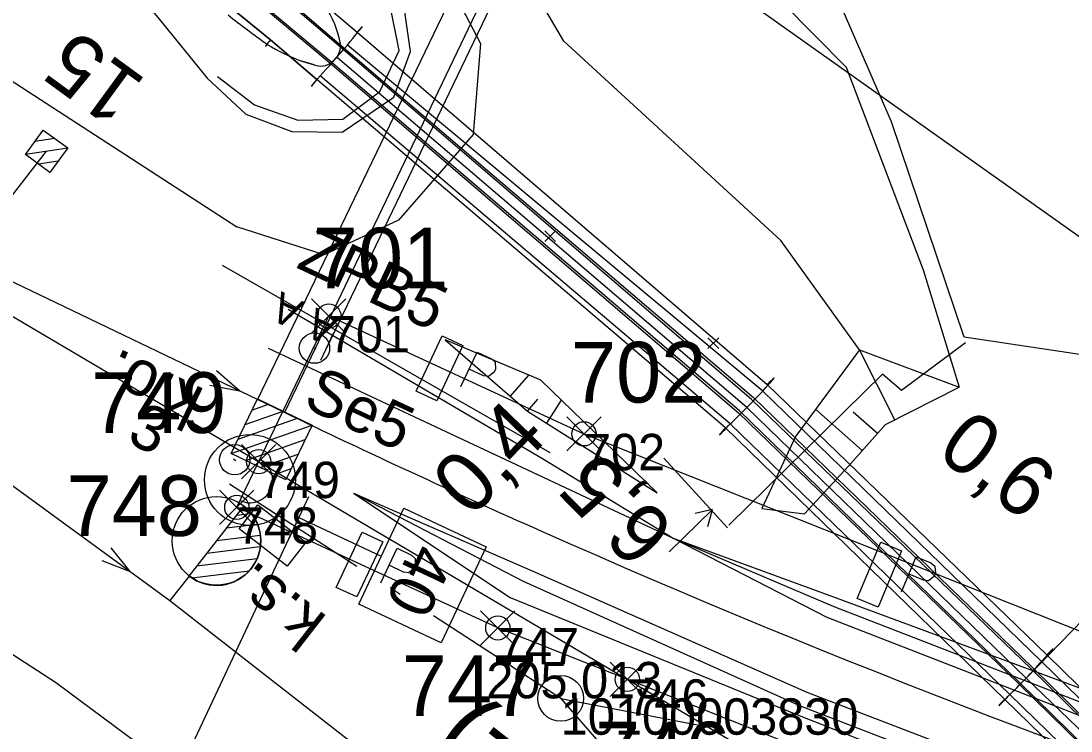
# Model space of a CAD drawing. Extents: x -800194 to -799078, y -1007177 to -1006597.
# Drawn here: x -799787.82 to -799753.2, y -1006976.93 to -1006953.52 of the extents above; entities that cross this region are included whole.
import ezdxf

# ---------------------------------------------------------------- set-up
doc = ezdxf.new("R2010")
doc.units = 0
for name, color, linetype in [('02_Osa_koleje', 7, 'Continuous'), ('_návrh', 7, 'Continuous'), ('_popvyt', 7, 'Continuous'), ('Obvod stavby', 7, 'Continuous'), ('Vrstva 11', 7, 'Continuous'), ('Vrstva 13', 7, 'Continuous'), ('Vrstva 16', 7, 'Continuous'), ('Vrstva 17', 7, 'Continuous'), ('Vrstva 18', 7, 'Continuous'), ('Vrstva 2', 7, 'Continuous'), ('Vrstva 25', 7, 'Continuous'), ('Vrstva 27', 7, 'Continuous'), ('Vrstva 3', 7, 'Continuous'), ('Vrstva 34', 7, 'Continuous'), ('Vrstva 36', 7, 'Continuous'), ('Vrstva 4', 7, 'Continuous'), ('Vrstva 48', 7, 'Continuous'), ('Vrstva 49', 7, 'Continuous'), ('Vrstva 5', 7, 'Continuous'), ('Vrstva 55', 7, 'Continuous'), ('Vrstva 6', 7, 'Continuous'), ('Vrstva 60', 7, 'Continuous'), ('Vrstva 61', 7, 'Continuous'), ('Vrstva 63', 7, 'Continuous')]:
    doc.layers.add(name, color=color, linetype=linetype)

msp = doc.modelspace()

# ---------------------------------------------------------------- linework, layer by layer
at = {"layer": '02_Osa_koleje'}
msp.add_lwpolyline([(-799770.682, -1006970.328), (-799769.768, -1006970.733), (-799768.852, -1006971.134), (-799767.934, -1006971.532), (-799767.016, -1006971.927), (-799766.096, -1006972.319), (-799765.175, -1006972.709), (-799764.252, -1006973.095), (-799763.329, -1006973.478), (-799762.404, -1006973.858), (-799761.478, -1006974.235), (-799760.55, -1006974.609), (-799759.621, -1006974.98), (-799758.692, -1006975.348), (-799757.761, -1006975.713), (-799756.828, -1006976.075), (-799755.895, -1006976.434), (-799754.96, -1006976.789), (-799754.025, -1006977.142), (-799753.088, -1006977.491)], dxfattribs=at)
msp.add_arc((-799645.745, -1006688.806), 308, 244.32513, 246.06876, dxfattribs=at)
at = {"layer": '_návrh'}
msp.add_line((-799791.14, -1006960.652), (-799779.191, -1006966.397), dxfattribs=at)
for points in [[(-799821.595, -1006948.007), (-799811.064, -1006954.324), (-799803.753, -1006958.707), (-799793.935, -1006964.581), (-799784.224, -1006971.671), (-799782.913, -1006972.63), (-799767.418, -1006984.719), (-799752.333, -1006998.173), (-799735.027, -1007015.997), (-799721.623, -1007030.81), (-799713.555, -1007039.726), (-799713.111, -1007040.218)], [(-799820.755, -1006954.001), (-799803.004, -1006964.743), (-799786.682, -1006975.322), (-799769.882, -1006987.807), (-799754.745, -1007000.643), (-799736.311, -1007017.261), (-799721.623, -1007030.81)]]:
    msp.add_lwpolyline(points, dxfattribs=at)
msp.add_circle((-799780.274, -1006968.65), 1.5, dxfattribs=at)
for start, end in [(334.3251, 64.3251), (244.3251, 334.3251)]:
    msp.add_arc((-799780.274, -1006968.65), 0.75, start, end, dxfattribs=at)
at = {"layer": 'Obvod stavby'}
for p, q in [((-799778.24, -1006963.808), (-799777.108, -1006962.676)), ((-799778.24, -1006962.676), (-799777.108, -1006963.808)), ((-799769.828, -1006967.695), (-799768.697, -1006966.564)), ((-799769.828, -1006966.564), (-799768.697, -1006967.695)), ((-799780.55, -1006968.614), (-799779.419, -1006967.483)), ((-799780.55, -1006967.483), (-799779.419, -1006968.614)), ((-799781.273, -1006970.117), (-799780.141, -1006968.985)), ((-799781.273, -1006968.985), (-799780.141, -1006970.117)), ((-799772.668, -1006974.093), (-799771.536, -1006972.962)), ((-799772.668, -1006972.962), (-799771.536, -1006974.093)), ((-799768.399, -1006975.79), (-799767.268, -1006974.659)), ((-799768.399, -1006974.659), (-799767.268, -1006975.79))]:
    msp.add_line(p, q, dxfattribs=at)
msp.add_lwpolyline([(-799664.426, -1006999.087), (-799684.601, -1006997.477), (-799704.619, -1006994.49), (-799724.386, -1006990.14), (-799749.554, -1006982.491), (-799772.102, -1006973.528), (-799780.707, -1006969.551), (-799777.674, -1006963.242), (-799769.263, -1006967.129), (-799747.228, -1006975.889), (-799722.648, -1006983.359), (-799703.35, -1006987.606), (-799683.806, -1006990.523), (-799664.228, -1006992.091)], dxfattribs=at)
for centre in [(-799777.674, -1006963.242), (-799769.263, -1006967.129), (-799779.985, -1006968.048), (-799780.707, -1006969.551), (-799772.102, -1006973.528), (-799767.833, -1006975.225)]:
    msp.add_circle(centre, 0.4, dxfattribs=at)
at = {"layer": 'Vrstva 11'}
for p, q in [((-799786.705, -1006957.392), (-799787.366, -1006957.495)), ((-799801.01, -1006975.832), (-799786.978, -1006957.812)), ((-799786.281, -1006957.705), (-799787.674, -1006957.923)), ((-799786.594, -1006958.133), (-799787.246, -1006958.235))]:
    msp.add_line(p, q, dxfattribs=at)
msp.add_lwpolyline([(-799786.869, -1006958.511), (-799787.677, -1006957.921), (-799787.087, -1006957.113), (-799786.279, -1006957.703)], close=True, dxfattribs=at)
at = {"layer": 'Vrstva 13'}
msp.add_line((-799766.453, -1006971.023), (-799765.026, -1006969.623), dxfattribs=at)
msp.add_lwpolyline([(-799765.172, -1006970.187), (-799765.026, -1006969.623), (-799765.593, -1006969.759)], dxfattribs=at)
at = {"layer": 'Vrstva 16'}
msp.add_line((-799778.157, -1006954.96), (-799778.565, -1006954.841), dxfattribs=at)
for points in [[(-799785.4, -1006950.909), (-799783.301, -1006953.407), (-799781.69, -1006955.406), (-799780.41, -1006956.591), (-799778.888, -1006957.162), (-799777.239, -1006957.179), (-799775.528, -1006956.024), (-799774.978, -1006954.519), (-799775.211, -1006952.901), (-799775.953, -1006951.439), (-799777.187, -1006950.172), (-799779.455, -1006948.919), (-799782.509, -1006947.186)], [(-799783.708, -1006948.669), (-799779.9, -1006952.065), (-799777.252, -1006954.333), (-799763.672, -1006965.935), (-799754.476, -1006974.829), (-799742.393, -1006986.703), (-799736.524, -1006991.578), (-799726.778, -1006999.642)], [(-799726.857, -1006999.659), (-799736.574, -1006991.623), (-799742.439, -1006986.725), (-799754.518, -1006974.879), (-799763.734, -1006965.993), (-799777.293, -1006954.374), (-799779.945, -1006952.099), (-799783.722, -1006948.693)], [(-799784.356, -1006949.5), (-799780.347, -1006952.62), (-799777.716, -1006954.827), (-799764.168, -1006966.436), (-799754.935, -1006975.363), (-799742.857, -1006987.188), (-799736.94, -1006992.081), (-799727.324, -1007000.028)], [(-799727.258, -1006999.988), (-799736.887, -1006992.032), (-799742.859, -1006987.132), (-799754.894, -1006975.337), (-799764.135, -1006966.374), (-799777.698, -1006954.783), (-799780.331, -1006952.581), (-799784.321, -1006949.462)], [(-799779.465, -1006951.506), (-799778.251, -1006952.583), (-799776.738, -1006953.884), (-799763.224, -1006965.504), (-799753.999, -1006974.421), (-799741.964, -1006986.204), (-799736.168, -1006991.012), (-799728.577, -1006997.215), (-799726.123, -1006999.163)], [(-799727.952, -1007000.326), (-799729.82, -1006998.717), (-799737.37, -1006992.486), (-799743.358, -1006987.594), (-799755.401, -1006975.883), (-799764.592, -1006966.926), (-799778.073, -1006955.449), (-799779.598, -1006954.142), (-799780.843, -1006953.125)]]:
    msp.add_lwpolyline(points, dxfattribs=at)
for centre, major_axis, ratio, start_param, end_param in [((-799780.886, -1006955.173), (2.894, 2.414), 0.919745, 5.794757, 6.192371), ((-799765.39, -1006947.43), (22.33, -7.783), 0.537883, 4.140419, 4.216217), ((-799775.114, -1006948.938), (-6.81, -2.765), 0.83994, 0.550611, 0.741846), ((-799777.883, -1006954.384), (0.368, 0.524), 0.895736, 3.328934, 5.426387)]:
    msp.add_ellipse(centre, major_axis=major_axis, ratio=ratio, start_param=start_param, end_param=end_param, dxfattribs=at)
at = {"layer": 'Vrstva 17'}
msp.add_line((-799766.63, -1006967.927), (-799764.528, -1006970.233), dxfattribs=at)
for points in [[(-799756.721, -1006963.941), (-799759.125, -1006956.836), (-799761.008, -1006952.49), (-799761.962, -1006949.962), (-799762.434, -1006943.507)], [(-799781.343, -1006955.343), (-799780.121, -1006956.276), (-799778.697, -1006956.784), (-799777.217, -1006956.75), (-799775.995, -1006955.84), (-799775.356, -1006954.486), (-799775.648, -1006953.011), (-799776.321, -1006951.673), (-799777.368, -1006950.593)], [(-799756.678, -1006964.125), (-799758.792, -1006965.704), (-799759.415, -1006965.167), (-799764.485, -1006970.145)], [(-799726.806, -1006975.491), (-799728.174, -1006980.607), (-799746.39, -1006975.498), (-799745.242, -1006970.318), (-799744.263, -1006965.815), (-799756.721, -1006963.941)]]:
    msp.add_lwpolyline(points, dxfattribs=at)
at = {"layer": 'Vrstva 18'}
for p, q in [((-799754.68, -1006975.182), (-799715.262, -1006934.616)), ((-799778.565, -1006954.841), (-799778.157, -1006954.96))]:
    msp.add_line(p, q, dxfattribs=at)
for points in [[(-799779.465, -1006951.506), (-799778.251, -1006952.583), (-799776.738, -1006953.884)], [(-799780.843, -1006953.125), (-799779.598, -1006954.142), (-799778.073, -1006955.449)], [(-799776.738, -1006953.884), (-799763.224, -1006965.504), (-799753.999, -1006974.421), (-799741.964, -1006986.204), (-799736.168, -1006991.012)], [(-799728.689, -1006997.417), (-799736.272, -1006991.186), (-799742.111, -1006986.385), (-799754.178, -1006974.631), (-799763.368, -1006965.72), (-799777.061, -1006954.31)], [(-799736.701, -1006991.694), (-799742.573, -1006986.82), (-799754.68, -1006975.182), (-799763.887, -1006966.256), (-799777.391, -1006954.732)], [(-799737.37, -1006992.486), (-799743.358, -1006987.594), (-799755.401, -1006975.883), (-799764.592, -1006966.926), (-799778.073, -1006955.449)], [(-799729.664, -1006998.596), (-799737.245, -1006992.341), (-799743.186, -1006987.438), (-799755.222, -1006975.72), (-799764.444, -1006966.802), (-799777.959, -1006955.323)]]:
    msp.add_lwpolyline(points, dxfattribs=at)
for centre, major_axis, ratio, start_param, end_param in [((-799780.886, -1006955.173), (2.894, 2.414), 0.919745, 5.794757, 6.192371), ((-799765.39, -1006947.43), (22.33, -7.783), 0.537883, 4.140419, 4.216217), ((-799777.816, -1006955.165), (1.245, 1.471), 0.015308, 5.345189, 6.145729), ((-799777.816, -1006955.216), (1.244, 1.519), 0.010626, 6.159788, 6.793595), ((-799777.882, -1006953.279), (-1.858, -1.106), 0.135621, 5.801514, 6.067534), ((-799778.587, -1006952.902), (-1.171, -1.446), 0.009799, 6.046537, 6.582716), ((-799775.114, -1006948.938), (-6.81, -2.765), 0.83994, 0.550611, 0.741846), ((-799777.883, -1006954.384), (0.368, 0.524), 0.895736, 3.328934, 5.426387), ((-799777.417, -1006954.672), (0.706, 0.807), 0.030898, 3.802387, 5.20436), ((-799777.09, -1006954.29), (-1.161, -1.379), 0.000515, 6.0585, 7.007599), ((-799776.577, -1006954.198), (-1.666, -1.496), 0.062742, 5.768794, 6.060563), ((-799764.209, -1006966.632), (1.225, 1.347), 0.00569, 5.462132, 6.45682), ((-799764.267, -1006966.931), (1.309, 1.64), 0.066438, 0.193143, 0.570602), ((-799763.899, -1006966.226), (0.719, 0.725), 0.028964, 3.823595, 5.514697), ((-799763.469, -1006965.755), (-1.321, -1.405), 0.014987, 5.711575, 6.53997), ((-799763.588, -1006965.716), (-1.214, -1.448), 0.032329, 0.280391, 0.750862), ((-799755.015, -1006975.474), (1.23, 1.269), 0.011168, 5.449588, 6.468473), ((-799755.131, -1006975.736), (1.35, 1.533), 0.01765, 0.183735, 0.556082), ((-799754.712, -1006975.133), (0.699, 0.732), 0.056068, 3.837002, 5.520083), ((-799754.422, -1006974.757), (-1.164, -1.342), 0.001186, 5.709743, 6.582824), ((-799754.595, -1006974.816), (0.979, 1.241), 0.059951, 3.363928, 3.944453)]:
    msp.add_ellipse(centre, major_axis=major_axis, ratio=ratio, start_param=start_param, end_param=end_param, dxfattribs=at)
at = {"layer": 'Vrstva 2'}
for p, q in [((-799756.904, -1006917.966), (-799780.025, -1006965.993)), ((-799782.282, -1006971.817), (-799780.481, -1006969.51)), ((-799780.715, -1006969.809), (-799780.242, -1006969.751)), ((-799781.042, -1006970.228), (-799780.034, -1006970.104)), ((-799781.368, -1006970.646), (-799779.935, -1006970.469)), ((-799781.695, -1006971.064), (-799779.932, -1006970.846)), ((-799782.021, -1006971.482), (-799780.038, -1006971.237)), ((-799782.283, -1006971.818), (-799782.913, -1006972.63)), ((-799782.282, -1006971.817), (-799782.282, -1006971.817)), ((-799782.188, -1006971.88), (-799780.304, -1006971.648))]:
    msp.add_line(p, q, dxfattribs=at)
for points in [[(-799781.6, -1006965.523), (-799780.617, -1006965.708), (-799781.376, -1006965.057)], [(-799785.157, -1006971.31), (-799784.224, -1006971.671), (-799784.852, -1006970.892)]]:
    msp.add_lwpolyline(points, dxfattribs=at)
msp.add_circle((-799781.376, -1006970.658), 1.462, dxfattribs=at)
msp.add_arc((-799781.382, -1006970.663), 1.464, 232.0587, 52.0195, dxfattribs=at)
at = {"layer": 'Vrstva 25'}
msp.add_lwpolyline([(-799778.434, -1006970.704), (-799779.049, -1006971.492), (-799780.626, -1006970.262), (-799780.011, -1006969.474), (-799778.434, -1006970.704)], dxfattribs=at)
at = {"layer": 'Vrstva 27'}
for p, q in [((-799778.191, -1006964.283), (-799778.101, -1006964.325)), ((-799780.817, -1006967.954), (-799780.737, -1006968.012))]:
    msp.add_line(p, q, dxfattribs=at)
for centre in [(-799778.146, -1006964.304), (-799780.777, -1006967.983)]:
    msp.add_circle(centre, 0.5, dxfattribs=at)
at = {"layer": 'Vrstva 3'}
for p, q in [((-799756.121, -1006918.343), (-799779.128, -1006966.408)), ((-799780.207, -1006966.345), (-799779.661, -1006966.153)), ((-799780.665, -1006967.302), (-799778.704, -1006966.611)), ((-799780.435, -1006966.823), (-799779.183, -1006966.382)), ((-799780.894, -1006967.78), (-799778.226, -1006966.84)), ((-799780.415, -1006968.009), (-799778.455, -1006967.318)), ((-799779.936, -1006968.238), (-799778.684, -1006967.797)), ((-799779.458, -1006968.467), (-799778.913, -1006968.275))]:
    msp.add_line(p, q, dxfattribs=at)
msp.add_lwpolyline([(-799780.03, -1006965.976), (-799778.226, -1006966.84), (-799779.09, -1006968.644), (-799780.894, -1006967.78)], close=True, dxfattribs=at)
at = {"layer": 'Vrstva 34'}
msp.add_line((-799781.191, -1006961.569), (-799770.384, -1006967.741), dxfattribs=at)
at = {"layer": 'Vrstva 36'}
for points in [[(-799773.933, -1006963.899), (-799773.259, -1006964.216), (-799774.115, -1006966.039), (-799774.789, -1006965.722)], [(-799776.571, -1006970.369), (-799775.897, -1006970.686), (-799776.753, -1006972.509), (-799777.427, -1006972.192)], [(-799759.474, -1006970.701), (-799758.787, -1006970.989), (-799759.566, -1006972.847), (-799760.253, -1006972.559)]]:
    msp.add_lwpolyline(points, close=True, dxfattribs=at)
for points in [[(-799773.318, -1006965.568), (-799772.784, -1006964.433), (-799772.312, -1006964.655), (-799772.192, -1006964.77), (-799772.178, -1006965), (-799772.225, -1006965.1), (-799772.413, -1006965.242), (-799772.576, -1006965.215), (-799773.048, -1006964.994)], [(-799775.956, -1006972.038), (-799775.422, -1006970.903), (-799774.95, -1006971.125), (-799774.83, -1006971.24), (-799774.816, -1006971.47), (-799774.863, -1006971.57), (-799775.051, -1006971.712), (-799775.214, -1006971.685), (-799775.686, -1006971.464)], [(-799758.789, -1006972.343), (-799758.304, -1006971.186), (-799757.823, -1006971.388), (-799757.698, -1006971.497), (-799757.674, -1006971.727), (-799757.717, -1006971.829), (-799757.899, -1006971.978), (-799758.062, -1006971.959), (-799758.543, -1006971.757)]]:
    msp.add_lwpolyline(points, dxfattribs=at)
at = {"layer": 'Vrstva 4'}
for points in [[(-799766.319, -1006970.565), (-799760.949, -1006972.542), (-799747.638, -1006977.46), (-799730.549, -1006982.982), (-799710.066, -1006987.578), (-799704.728, -1006988.346), (-799693.001, -1006990.373), (-799682.434, -1006991.64), (-799671.27, -1006992.619), (-799659.31, -1006993.026), (-799648.69, -1006993.125), (-799637.398, -1006992.704), (-799625.913, -1006992.175), (-799614.965, -1006990.831), (-799603.911, -1006989.312), (-799592.728, -1006987.172), (-799581.605, -1006984.547), (-799570.583, -1006981.598), (-799559.909, -1006978.216), (-799542.956, -1006972.25), (-799531.79, -1006967.658), (-799521.285, -1006962.191), (-799511.236, -1006957.129)], [(-799779.678, -1006964.304), (-799766.319, -1006970.565), (-799761.253, -1006973.176), (-799747.77, -1006978.421), (-799730.774, -1006983.8), (-799710.333, -1006988.709), (-799704.916, -1006989.741), (-799693.131, -1006991.407), (-799682.585, -1006992.929), (-799671.325, -1006993.879), (-799659.363, -1006994.45), (-799648.66, -1006994.501), (-799637.23, -1006994.127), (-799626.066, -1006993.335), (-799614.788, -1006992.17), (-799603.669, -1006990.506), (-799592.467, -1006988.452), (-799581.281, -1006985.916), (-799570.22, -1006982.998), (-799559.296, -1006979.606), (-799542.375, -1006973.485), (-799531.236, -1006968.774), (-799520.48, -1006963.762), (-799510.394, -1006958.536)], [(-799776.864, -1006969.085), (-799770.965, -1006971.646), (-799761.91, -1006975.649), (-799748.544, -1006980.777), (-799731.457, -1006986.215), (-799711.132, -1006991.054), (-799705.482, -1006992.16), (-799693.53, -1006994.084), (-799682.801, -1006995.384), (-799671.514, -1006996.319), (-799659.449, -1006996.851), (-799648.588, -1006996.949), (-799637.262, -1006996.573), (-799625.835, -1006995.773), (-799614.546, -1006994.586), (-799603.199, -1006992.945), (-799591.969, -1006990.857), (-799580.647, -1006988.335), (-799569.534, -1006985.311), (-799558.557, -1006981.947), (-799541.405, -1006975.739), (-799530.263, -1006971.071), (-799519.455, -1006966), (-799509.248, -1006960.724)], [(-799776.864, -1006969.085), (-799771.262, -1006971.982), (-799762.131, -1006976.093), (-799748.706, -1006981.286), (-799731.51, -1006986.353), (-799711.222, -1006991.459), (-799705.527, -1006992.587), (-799693.582, -1006994.543), (-799682.85, -1006995.904), (-799671.5, -1006996.805), (-799659.556, -1006997.356), (-799648.616, -1006997.341), (-799637.276, -1006997.071), (-799625.828, -1006996.297), (-799614.43, -1006995.109), (-799603.18, -1006993.475), (-799591.849, -1006991.264), (-799580.564, -1006988.698), (-799569.449, -1006985.746), (-799558.385, -1006982.386), (-799541.268, -1006976.227), (-799530.102, -1006971.505), (-799519.398, -1006966.36), (-799509.087, -1006961.127)], [(-799779.011, -1006963.023), (-799770.632, -1006967.944), (-799766.319, -1006970.565), (-799761.021, -1006972.82), (-799747.748, -1006977.966), (-799730.719, -1006983.271), (-799710.195, -1006988.108), (-799704.765, -1006989.181), (-799693.072, -1006990.965), (-799682.554, -1006992.238), (-799671.266, -1006993.222), (-799659.388, -1006993.765), (-799648.658, -1006993.824), (-799637.385, -1006993.531), (-799625.769, -1006992.728), (-799614.9, -1006991.542), (-799603.91, -1006989.963), (-799592.572, -1006987.892), (-799581.421, -1006985.419), (-799570.327, -1006982.332), (-799559.429, -1006979.066), (-799542.601, -1006973.013), (-799531.454, -1006968.25), (-799520.744, -1006963.214)], [(-799776.864, -1006969.085), (-799771.693, -1006972.522), (-799762.217, -1006976.394), (-799748.898, -1006981.647), (-799733.68, -1006986.66), (-799728.795, -1006987.945), (-799711.349, -1006992.599), (-799705.744, -1006994.116), (-799693.689, -1006996.09), (-799689.347, -1006996.226), (-799688.222, -1006996.296), (-799683.105, -1006997.407), (-799671.667, -1006998.275)]]:
    msp.add_lwpolyline(points, dxfattribs=at)
at = {"layer": 'Vrstva 48'}
for p, q in [((-799759.008, -1006966.666), (-799760.173, -1006964.364)), ((-799771.688, -1006965.89), (-799771.083, -1006965.192)), ((-799771.121, -1006966.381), (-799770.781, -1006965.989)), ((-799770.486, -1006966.781), (-799770.005, -1006966.018)), ((-799760.084, -1006967.683), (-799761.624, -1006966.32)), ((-799759.587, -1006967.122), (-799760.381, -1006966.419))]:
    msp.add_line(p, q, dxfattribs=at)
at = {"layer": 'Vrstva 49'}
for p, q in [((-799770.553, -1006960.435), (-799770.199, -1006960.789)), ((-799770.553, -1006960.789), (-799770.199, -1006960.435)), ((-799765.172, -1006963.963), (-799764.818, -1006964.317)), ((-799765.172, -1006964.317), (-799764.818, -1006963.963)), ((-799760.173, -1006964.364), (-799756.886, -1006965.592))]:
    msp.add_line(p, q, dxfattribs=at)
for points in [[(-799787.714, -1006940.466), (-799779.601, -1006945.884), (-799774.772, -1006950.23), (-799772.678, -1006954.259), (-799772.914, -1006957.256), (-799775.374, -1006960.084), (-799777.823, -1006961.225), (-799780.709, -1006960.303)], [(-799809.896, -1006941.363), (-799780.709, -1006960.303)], [(-799777.554, -1006942.387), (-799773.745, -1006944.786), (-799766.953, -1006948.615), (-799760.613, -1006955.042), (-799758.076, -1006961.72), (-799756.886, -1006965.592)], [(-799760.173, -1006964.364), (-799762.769, -1006960.758), (-799769.93, -1006954.183), (-799773.856, -1006947.464), (-799779.16, -1006943.327)], [(-799784.51, -1006949.428), (-799784.321, -1006949.462), (-799784.796, -1006950.091), (-799784.795, -1006950.113), (-799785.4, -1006950.909), (-799783.301, -1006953.407), (-799781.69, -1006955.406), (-799780.41, -1006956.591), (-799778.888, -1006957.162), (-799777.239, -1006957.179), (-799775.528, -1006956.024), (-799774.978, -1006954.519), (-799775.211, -1006952.901), (-799775.953, -1006951.439), (-799777.187, -1006950.172), (-799779.455, -1006948.919), (-799782.509, -1006947.186), (-799783.217, -1006948.059), (-799783.233, -1006948.077), (-799783.722, -1006948.693), (-799783.829, -1006948.476)], [(-799773.843, -1006964.024), (-799771.12, -1006966.382), (-799766.849, -1006969.075)], [(-799766.849, -1006969.075), (-799770.685, -1006965.36), (-799773.843, -1006964.024)], [(-799760.173, -1006964.364), (-799762.289, -1006967.216), (-799763.402, -1006969.589)], [(-799763.402, -1006969.589), (-799761.992, -1006969.771), (-799760.55, -1006968.21), (-799759.325, -1006966.826), (-799756.886, -1006965.592)]]:
    msp.add_lwpolyline(points, dxfattribs=at)
at = {"layer": 'Vrstva 5'}
for p, q in [((-799778.34, -1006969.207), (-799778.978, -1006970.565)), ((-799796.24, -1007007.322), (-799778.659, -1006969.886)), ((-799778.659, -1006969.886), (-799775.944, -1006971.161))]:
    msp.add_line(p, q, dxfattribs=at)
msp.add_lwpolyline([(-799776.687, -1006972.745), (-799775.2, -1006969.577), (-799772.484, -1006970.853), (-799773.972, -1006974.021)], close=True, dxfattribs=at)
at = {"layer": 'Vrstva 55'}
msp.add_line((-799785.23, -1006937.71), (-799741.57, -1006968.68), dxfattribs=at)
msp.add_lwpolyline([(-799785.23, -1006937.71), (-799791.69, -1006959.99), (-799791.97, -1006960.97), (-799746.76, -1006987.67), (-799745.68, -1006988.03), (-799733.28, -1006992.13)], dxfattribs=at)
at = {"layer": 'Vrstva 6'}
msp.add_line((-799777.933, -1006964.695), (-799777.507, -1006963.789), dxfattribs=at)
msp.add_lwpolyline([(-799752.416, -1006919.71), (-799759.639, -1006934.751), (-799762.823, -1006933.223), (-799777.74, -1006964.286)], dxfattribs=at)
at = {"layer": 'Vrstva 60'}
for p, q in [((-799777.674, -1006963.242), (-799777.674, -1006963.242)), ((-799769.263, -1006967.129), (-799769.263, -1006967.129)), ((-799779.985, -1006968.048), (-799779.985, -1006968.048)), ((-799780.707, -1006969.551), (-799780.707, -1006969.551)), ((-799772.102, -1006973.528), (-799772.102, -1006973.528)), ((-799767.833, -1006975.225), (-799767.833, -1006975.225)), ((-799770.028, -1006975.851), (-799770.028, -1006975.851))]:
    msp.add_line(p, q, dxfattribs=at)
at = {"layer": 'Vrstva 63'}
for p, q in [((-799776.745, -1006971.506), (-799780.943, -1006968.79)), ((-799775.318, -1006972.429), (-799775.653, -1006972.212)), ((-799770.028, -1006975.851), (-799774.226, -1006973.135)), ((-799769.989, -1006975.882), (-799770.067, -1006975.82)), ((-799770.028, -1006975.851), (-799765.12, -1006976.804)), ((-799770.028, -1006975.851), (-799766.738, -1006979.616))]:
    msp.add_line(p, q, dxfattribs=at)
msp.add_circle((-799770.028, -1006975.851), 0.756, dxfattribs=at)

# ---------------------------------------------------------------- texts
at = {"layer": '_popvyt'}
msp.add_text('3', height=1.5, rotation=334.3251, dxfattribs=at).set_placement((-799784.386, -1006967.382))
at = {"layer": 'Obvod stavby'}
for s, p in [('701', (-799778.202, -1006962.333)), ('702', (-799769.692, -1006966.098)), ('749', (-799785.512, -1006967.101)), ('748', (-799786.32, -1006970.497)), ('747', (-799775.271, -1006976.434)), ('746', (-799768.895, -1006978.625))]:
    msp.add_text(s, height=2, rotation=360, dxfattribs=at).set_placement(p)
at = {"layer": 'Vrstva 11'}
msp.add_text('15', height=2, rotation=143.8668, dxfattribs=at).set_placement((-799783.638, -1006955.492))
at = {"layer": 'Vrstva 13'}
msp.add_text('6,5', height=2, rotation=134.4646, dxfattribs=at).set_placement((-799766.184, -1006970.262))
at = {"layer": 'Vrstva 25'}
msp.add_text('k.s.', height=1.5, rotation=142.0391, dxfattribs=at).set_placement((-799777.68, -1006973.186))
at = {"layer": 'Vrstva 27'}
for s, rotation, p in [('ZPB5', 334.8436, (-799778.789, -1006961.631)), ('k.o.', 154.3489, (-799781.715, -1006965.686))]:
    msp.add_text(s, height=1.5, rotation=rotation, dxfattribs=at).set_placement(p)
at = {"layer": 'Vrstva 48'}
for s, rotation, p in [('0,4', 45.9181, (-799772.985, -1006969.943)), ('0,6', 323.427, (-799757.699, -1006967.832))]:
    msp.add_text(s, height=2, rotation=rotation, dxfattribs=at).set_placement(p)
at = {"layer": 'Vrstva 5'}
msp.add_text('40', height=1.5, rotation=244.8436, dxfattribs=at).set_placement((-799774.876, -1006970.653))
at = {"layer": 'Vrstva 6'}
for s, height, rotation, p in [('A A ', 1, 154.8436, (-799777.295, -1006963.337)), ('Se5', 1.5, 334.8436, (-799778.573, -1006966.216))]:
    msp.add_text(s, height=height, rotation=rotation, dxfattribs=at).set_placement(p)
at = {"layer": 'Vrstva 60'}
for s, p in [('701', (-799777.674, -1006964.442)), ('702', (-799769.263, -1006968.329)), ('749', (-799779.985, -1006969.248)), ('748', (-799780.707, -1006970.751)), ('747', (-799772.102, -1006974.728)), ('746', (-799767.833, -1006976.425)), ('10100003830', (-799770.028, -1006977.051))]:
    msp.add_text(s, height=1.2, dxfattribs=at).set_placement(p)
at = {"layer": 'Vrstva 61'}
msp.add_text('205.013', height=1.2, dxfattribs=at).set_placement((-799772.48, -1006975.851))
at = {"layer": 'Vrstva 63'}
msp.add_text('(TÚ 0101)', height=2.4, rotation=142.0391, dxfattribs=at).set_placement((-799761.816, -1006984.928))

doc.saveas('drawing.dxf')
